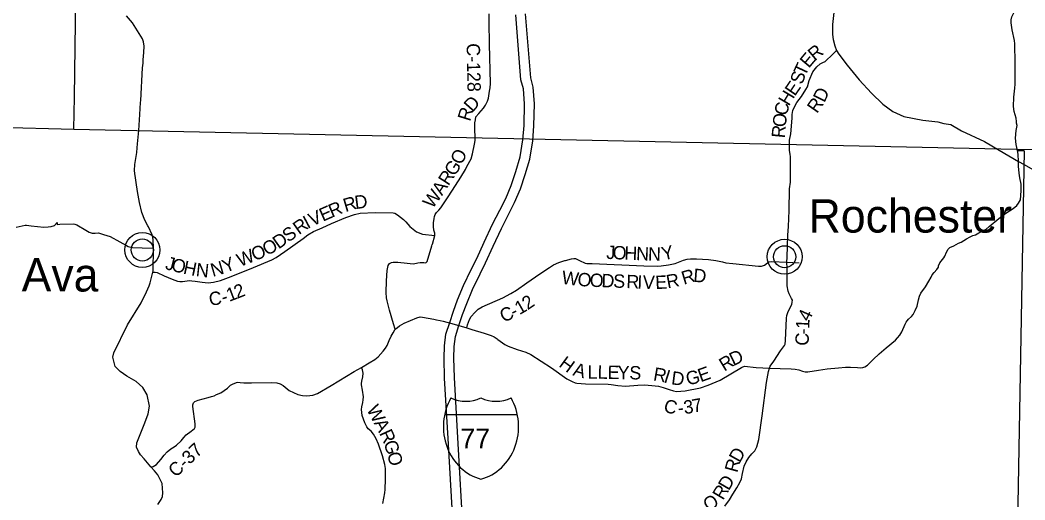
# Model space of a CAD drawing. Extents: x -452339 to 6403467, y -1 to 1814750.
# Drawn here: x -379658 to -357078, y 1620353 to 1631137 of the extents above; entities that cross this region are included whole.
import ezdxf

# ---------------------------------------------------------------- set-up
doc = ezdxf.new("R2010")
doc.units = 0
for name, color, linetype in [('Default', 7, 'Continuous'), ('GM_X_Adjacent_County_Text', 7, 'Continuous'), ('GM_X_County', 7, 'Continuous'), ('GM_X_County_Road', 7, 'Continuous'), ('GM_X_County_Road_Text', 7, 'Continuous'), ('GM_X_Major_River', 7, 'Continuous'), ('GM_X_Minor_Lake_Text', 7, 'Continuous'), ('GM_X_Section', 7, 'Continuous'), ('GM_X_Section_Text', 7, 'Continuous')]:
    doc.layers.add(name, color=color, linetype=linetype)

msp = doc.modelspace()

# ---------------------------------------------------------------- linework, layer by layer
at = {"layer": 'Default'}
for points in [[(-357270, 1628817), (-357270, 1628818), (-357265, 1628856), (-357275, 1628936), (-357318, 1629084), (-357332, 1629193), (-357324, 1629407), (-357306, 1629605), (-357300, 1629697), (-357296, 1630170), (-357303, 1630602), (-357311, 1630676), (-357363, 1630918), (-357387, 1631075), (-357387, 1631139), (-357373, 1631213), (-357301, 1631343), (-357237, 1631443), (-357192, 1631553), (-357162, 1631726), (-357141, 1632254)], [(-369434, 1628434), (-369431, 1628459), (-369440, 1628726), (-369439, 1628828), (-369421, 1628897), (-369414, 1628966), (-369352, 1629041), (-369245, 1629156), (-369196, 1629226), (-369154, 1629311), (-369135, 1629385), (-369106, 1629542), (-369092, 1629616), (-369087, 1629714), (-369109, 1630593), (-369115, 1631092), (-369120, 1631274)], [(-357224, 1627958), (-357232, 1628120), (-357244, 1628204), (-357275, 1628344), (-357290, 1628486), (-357272, 1628652), (-357252, 1628766), (-357270, 1628817)], [(-370394, 1626096), (-370393, 1626098), (-370340, 1626299), (-370341, 1626349), (-370357, 1626413), (-370368, 1626499), (-370364, 1626579), (-370351, 1626676), (-370345, 1626724), (-370330, 1626768), (-370298, 1626814), (-370248, 1626863), (-370203, 1626921), (-370039, 1627165), (-369872, 1627423), (-369756, 1627608), (-369647, 1627777), (-369616, 1627849), (-369523, 1628022), (-369493, 1628130), (-369445, 1628347), (-369434, 1628434)], [(-362819, 1623315), (-362801, 1623357), (-362721, 1623473), (-362569, 1623700), (-362479, 1623824), (-362465, 1623852), (-362456, 1623938), (-362436, 1624435), (-362426, 1624501), (-362396, 1624591), (-362314, 1624744), (-362306, 1624794), (-362302, 1624840), (-362322, 1624882), (-362378, 1624988), (-362398, 1625046), (-362419, 1625168), (-362423, 1625559), (-362431, 1625695), (-362423, 1625807), (-362402, 1626306), (-362388, 1626500), (-362372, 1626854), (-362370, 1627347), (-362345, 1627497), (-362342, 1627996), (-362345, 1628066), (-362353, 1628122), (-362367, 1628205)], [(-357203, 1627695), (-357223, 1627856), (-357224, 1627958)], [(-362819, 1623315), (-362581, 1623307), (-362333, 1623297), (-362237, 1623292), (-362157, 1623276), (-362075, 1623250), (-362015, 1623234), (-361955, 1623232), (-361715, 1623266), (-361523, 1623301), (-361269, 1623321), (-361111, 1623335), (-360995, 1623333), (-360836, 1623330), (-360776, 1623322), (-360722, 1623328), (-360678, 1623342), (-360618, 1623378), (-360490, 1623507), (-360350, 1623635), (-360196, 1623773), (-359988, 1623944), (-359940, 1623994), (-359887, 1624054), (-359841, 1624134), (-359767, 1624305), (-359745, 1624349), (-359727, 1624377), (-359693, 1624417), (-359629, 1624477), (-359591, 1624521), (-359545, 1624608), (-359501, 1624706), (-359467, 1624848), (-359443, 1624934), (-359417, 1624996), (-359314, 1625145), (-359238, 1625267), (-359184, 1625361), (-359158, 1625413), (-359118, 1625467), (-359058, 1625532), (-359022, 1625584), (-359020, 1625612), (-358990, 1625678), (-358898, 1625796), (-358880, 1625830), (-358842, 1625924), (-358799, 1625987), (-358761, 1626029), (-358677, 1626067), (-358569, 1626121), (-358511, 1626147), (-358393, 1626219), (-358311, 1626264), (-358245, 1626292), (-358185, 1626314), (-358113, 1626352), (-358067, 1626380), (-357993, 1626414), (-357945, 1626438), (-357881, 1626495), (-357666, 1626675), (-357504, 1626795), (-357340, 1626906), (-357258, 1626972), (-357222, 1627020), (-357179, 1627097), (-357169, 1627198), (-357164, 1627309), (-357164, 1627451), (-357191, 1627594), (-357203, 1627695)], [(-376673, 1625468), (-376626, 1625470), (-376581, 1625461), (-376421, 1625392), (-376239, 1625317), (-376118, 1625268), (-376068, 1625262), (-376010, 1625265), (-375906, 1625278), (-375851, 1625282), (-375797, 1625275), (-375726, 1625267), (-375668, 1625262), (-375566, 1625248), (-375432, 1625235), (-375313, 1625244), (-375155, 1625284), (-374912, 1625374), (-374415, 1625580), (-374003, 1625747), (-373903, 1625800), (-373712, 1625936), (-373294, 1626228), (-373189, 1626313), (-373064, 1626388), (-372870, 1626471), (-372661, 1626567), (-372340, 1626702), (-372143, 1626764), (-372013, 1626795), (-371675, 1626811), (-371271, 1626807), (-371235, 1626797), (-371179, 1626761), (-371044, 1626652), (-370992, 1626602), (-370897, 1626495), (-370747, 1626376), (-370616, 1626325), (-370340, 1626299)], [(-379747, 1626481), (-379546, 1626525), (-379514, 1626529), (-379410, 1626515), (-379125, 1626484), (-379027, 1626488), (-378958, 1626495), (-378886, 1626520), (-378822, 1626590), (-378822, 1626546), (-378766, 1626551), (-378467, 1626556), (-378428, 1626547), (-378382, 1626533), (-378180, 1626413), (-378105, 1626372), (-378039, 1626351), (-377969, 1626350), (-377899, 1626352), (-377781, 1626320), (-377634, 1626276), (-377416, 1626156), (-377270, 1626068), (-377226, 1626047), (-377169, 1626035), (-377131, 1626027), (-376912, 1626020), (-376659, 1626013)], [(-371227, 1624187), (-371266, 1624309), (-371354, 1624621), (-371409, 1624824), (-371426, 1624892), (-371429, 1625011), (-371421, 1625279), (-371408, 1625510), (-371385, 1625624), (-371359, 1625664), (-371312, 1625689), (-371272, 1625697), (-371172, 1625694), (-370958, 1625671), (-370890, 1625664), (-370820, 1625662), (-370720, 1625681), (-370670, 1625686), (-370582, 1625686), (-370542, 1625683), (-370530, 1625689), (-370512, 1625709), (-370403, 1626062), (-370394, 1626096)], [(-367403, 1625734), (-367265, 1625773), (-367215, 1625780), (-367179, 1625777), (-367089, 1625736), (-366960, 1625677), (-366923, 1625665), (-366803, 1625663), (-365639, 1625616), (-365325, 1625606), (-365251, 1625611), (-365089, 1625634), (-364934, 1625669), (-364749, 1625743), (-364666, 1625764), (-364590, 1625774), (-364458, 1625774), (-364185, 1625755), (-364021, 1625736), (-363871, 1625700), (-363798, 1625682), (-363640, 1625667), (-363063, 1625603), (-362997, 1625604), (-362932, 1625631), (-362864, 1625683), (-362833, 1625703), (-362767, 1625710), (-362431, 1625695)], [(-369615, 1624217), (-369603, 1624288), (-369557, 1624408), (-369522, 1624472), (-369440, 1624568), (-369363, 1624637), (-369274, 1624689), (-368810, 1624898), (-368628, 1624991), (-368503, 1625066), (-368270, 1625228), (-368078, 1625364), (-367997, 1625421), (-367762, 1625580), (-367669, 1625636), (-367554, 1625690), (-367415, 1625730), (-367403, 1625734)], [(-362431, 1625695), (-362154, 1625682)], [(-376718, 1621099), (-376664, 1621102), (-376628, 1621126), (-376590, 1621152), (-376496, 1621260), (-376422, 1621355), (-376350, 1621433), (-376270, 1621501), (-376198, 1621547), (-376141, 1621583), (-376035, 1621684), (-375979, 1621756), (-375925, 1621812), (-375815, 1621896), (-375741, 1621955), (-375723, 1621985), (-375727, 1622059), (-375779, 1622455), (-375773, 1622493), (-375760, 1622531), (-375732, 1622566), (-375658, 1622598), (-375432, 1622654), (-375354, 1622678), (-375300, 1622694), (-375244, 1622719), (-375150, 1622759), (-375070, 1622809), (-374998, 1622863), (-374968, 1622893), (-374928, 1622931), (-374888, 1622955), (-374796, 1622988), (-374764, 1622996), (-374710, 1622990), (-374630, 1622986), (-374458, 1622986), (-374013, 1622991), (-373885, 1622981), (-373817, 1622965), (-373749, 1622923), (-373613, 1622813), (-373416, 1622719), (-373315, 1622697), (-373213, 1622692), (-373083, 1622710), (-372977, 1622744), (-372671, 1622923), (-372151, 1623236), (-371984, 1623332), (-371812, 1623433), (-371686, 1623509), (-371614, 1623565), (-371496, 1623698), (-371446, 1623764), (-371408, 1623820), (-371364, 1623932), (-371322, 1624031), (-371276, 1624107), (-371227, 1624187), (-371175, 1624231), (-371135, 1624267), (-371027, 1624325), (-370745, 1624442), (-370671, 1624464), (-370617, 1624462), (-370359, 1624415), (-370301, 1624402), (-370301, 1624402)], [(-370301, 1624402), (-370215, 1624383), (-370153, 1624369), (-369900, 1624305), (-369615, 1624217), (-369507, 1624182), (-369231, 1624102), (-369073, 1624050), (-369007, 1624020), (-368936, 1623972), (-368936, 1623971)], [(-368936, 1623971), (-368919, 1623960), (-368761, 1623848), (-368693, 1623810), (-368485, 1623737), (-368293, 1623675), (-368179, 1623619), (-367715, 1623325), (-367371, 1623075), (-367249, 1623011), (-367187, 1622985), (-367143, 1622973), (-366951, 1622964), (-366441, 1622953), (-366377, 1622943), (-366229, 1622921), (-366053, 1622911), (-365779, 1622934), (-365621, 1622942), (-365388, 1622920), (-365314, 1622906), (-365206, 1622882), (-365070, 1622832), (-364976, 1622807), (-364906, 1622793), (-364712, 1622805), (-364370, 1622872), (-364198, 1622928), (-363924, 1623045), (-363447, 1623332), (-363429, 1623340), (-363377, 1623356), (-363119, 1623330), (-362819, 1623315)], [(-371505, 1620272), (-371461, 1620511), (-371453, 1620585), (-371449, 1620817), (-371450, 1621060), (-371464, 1621148), (-371514, 1621340), (-371600, 1621604), (-371656, 1621728), (-371714, 1621829), (-371770, 1621901), (-371834, 1621951), (-371868, 1621995), (-371910, 1622083), (-371967, 1622249), (-371981, 1622317), (-371989, 1622383), (-371981, 1622445), (-371953, 1622545), (-371945, 1622603), (-371943, 1622669), (-371963, 1622816), (-371985, 1622940), (-371987, 1622972), (-371981, 1623022), (-371959, 1623120), (-371949, 1623200), (-371961, 1623274), (-371984, 1623332)], [(-363820, 1620210), (-363716, 1620354), (-363640, 1620485), (-363550, 1620623), (-363482, 1620745), (-363448, 1620828), (-363426, 1620948), (-363387, 1621108), (-363345, 1621212), (-363285, 1621303), (-363217, 1621391), (-363149, 1621459), (-363101, 1621545), (-363055, 1621710), (-362980, 1622245), (-362882, 1622990), (-362837, 1623237), (-362819, 1623315)]]:
    msp.add_lwpolyline(points, dxfattribs=at)
for centre, major_axis, start_param, end_param in [((-369055, 1622001), (0, -1211), 4.15077, 6.05619), ((-369639, 1623536), (0, -966), 5.88324, 6.683049), ((-369546, 1622001), (0, -1211), 0.227007, 2.13242), ((-368962, 1623536), (0, -966), 5.883359, 6.683012)]:
    msp.add_ellipse(centre, major_axis=major_axis, ratio=0.9, start_param=start_param, end_param=end_param, dxfattribs=at)
at = {"layer": 'GM_X_County_Road'}
for points in [[(-361353, 1631446), (-361401, 1631037), (-361398, 1630812), (-361384, 1630698), (-361347, 1630556), (-361309, 1630456), (-361259, 1630372), (-361075, 1630126), (-360803, 1629795), (-360524, 1629493), (-360268, 1629246), (-360049, 1629083), (-359797, 1628970), (-359370, 1628890), (-359033, 1628851), (-358900, 1628816), (-358744, 1628790), (-358501, 1628647), (-357982, 1628410), (-357655, 1628213), (-357224, 1627958), (-357097, 1627889), (-356492, 1627544)], [(-369913, 1619506), (-370040, 1621735), (-370119, 1623092), (-370131, 1623539), (-370122, 1623818), (-370089, 1624076), (-370004, 1624339), (-369920, 1624594), (-369825, 1624848), (-369691, 1625170), (-369519, 1625534), (-369394, 1625777), (-369226, 1626146), (-369039, 1626549), (-368876, 1626866), (-368744, 1627128), (-368623, 1627420), (-368520, 1627733), (-368418, 1628062), (-368357, 1628447), (-368330, 1628770), (-368321, 1629253), (-368344, 1629595), (-368402, 1629796), (-368516, 1631255)], [(-369693, 1619518), (-369820, 1621748), (-369899, 1623102), (-369911, 1623538), (-369902, 1623800), (-369873, 1624028), (-369795, 1624271), (-369713, 1624521), (-369621, 1624767), (-369490, 1625080), (-369321, 1625437), (-369196, 1625681), (-369026, 1626054), (-368842, 1626452), (-368680, 1626767), (-368544, 1627036), (-368416, 1627344), (-368310, 1627666), (-368203, 1628012), (-368138, 1628421), (-368110, 1628758), (-368101, 1629258), (-368126, 1629633), (-368184, 1629836), (-368297, 1631275)]]:
    msp.add_lwpolyline(points, dxfattribs=at)
at = {"layer": 'GM_X_County_Road_Text'}
for centre, radius in [((-376909, 1625971), 393), ((-376909, 1625971), 249), ((-362476, 1625817), 393), ((-362476, 1625817), 249)]:
    msp.add_circle(centre, radius, dxfattribs=at)
at = {"layer": 'GM_X_Major_River'}
for points in [[(-377024, 1628266), (-377018, 1628356), (-376992, 1628652), (-376965, 1629012), (-376949, 1629285), (-376943, 1629327), (-376906, 1630063), (-376895, 1630171), (-376889, 1630245), (-376875, 1630412), (-376866, 1630551), (-376886, 1630647), (-376907, 1630715), (-377132, 1631076), (-377263, 1631230)], [(-376760, 1625168), (-376735, 1625232), (-376673, 1625468), (-376664, 1625501), (-376659, 1626013), (-376667, 1626200), (-376677, 1626252), (-376688, 1626311), (-376772, 1626491), (-376784, 1626512), (-376855, 1626643), (-376925, 1626813), (-376976, 1627035), (-377017, 1627282), (-377049, 1627489), (-377067, 1627594), (-377079, 1627688), (-377088, 1627757), (-377082, 1627889), (-377075, 1627933), (-377031, 1628164), (-377024, 1628266)], [(-376563, 1620247), (-376487, 1620363), (-376459, 1620433), (-376449, 1620509), (-376466, 1620722), (-376560, 1620914), (-376634, 1621008), (-376718, 1621099), (-376870, 1621274), (-376954, 1621366), (-376999, 1621438), (-377043, 1621541), (-377034, 1621639), (-376942, 1621864), (-376855, 1622085), (-376782, 1622286), (-376746, 1622461), (-376805, 1622717), (-376902, 1622883), (-377053, 1623015), (-377258, 1623132), (-377408, 1623239), (-377523, 1623349), (-377570, 1623560), (-377550, 1623657), (-377242, 1624285), (-376938, 1624780), (-376814, 1625027), (-376760, 1625168)]]:
    msp.add_lwpolyline(points, dxfattribs=at)
at = {"layer": 'GM_X_Minor_Lake_Text'}
msp.add_line((-370115, 1622274), (-368484, 1622274), dxfattribs=at)
at = {"layer": 'GM_X_Section'}
msp.add_lwpolyline([(-362367, 1628205), (-362367, 1628209), (-362369, 1628293), (-362367, 1628437), (-362336, 1628580), (-362304, 1628929), (-362308, 1629015), (-362290, 1629107), (-362250, 1629203), (-362204, 1629284), (-362152, 1629350), (-362096, 1629418), (-362002, 1629574), (-361966, 1629636), (-361927, 1629779), (-361845, 1629977), (-361755, 1630089), (-361679, 1630157), (-361615, 1630181), (-361569, 1630208), (-361527, 1630240), (-361429, 1630336), (-361309, 1630456)], dxfattribs=at)
at = {"layer": 'GM_X_Section_Text'}
for p, q in [((-378437, 1629407), (-378391, 1632815)), ((-378448, 1628686), (-378437, 1629407)), ((-383695, 1628810), (-378448, 1628686)), ((-378448, 1628686), (-345663, 1627986)), ((-357093, 1628200), (-357520, 1603979)), ((-357244, 1628204), (-357093, 1628200)), ((-357093, 1628200), (-357244, 1628204))]:
    msp.add_line(p, q, dxfattribs=at)

# ---------------------------------------------------------------- texts
at = {"layer": 'Default'}
msp.add_text('77', height=447.7, dxfattribs=at).set_placement((-369763, 1621510))
at = {"layer": 'GM_X_Adjacent_County_Text'}
for s, p in [('Rochester', (-361939, 1626361)), ('Ava', (-379624, 1625037))]:
    msp.add_text(s, height=750, rotation=0, dxfattribs=at).set_placement(p)
at = {"layer": 'GM_X_County'}
for s, rotation, p in [('C-128', 271.1062, (-369624, 1630614)), ('R', 39.7046, (-361800, 1630204)), ('E', 50.0035, (-361934, 1630042)), ('T', 65.0949, (-362017, 1629856)), ('S', 70.4668, (-362082, 1629672)), ('E', 55.5539, (-362248, 1629412)), ('D', 48.6523, (-369491, 1629052)), ('H', 58.8932, (-362382, 1629189)), ('D', 63.867, (-361585, 1629268)), ('R', 72.6895, (-369548, 1628846)), ('C', 77.0893, (-362427, 1628973)), ('R', 55.4038, (-361749, 1629024)), ('O', 84.3006, (-362452, 1628720)), ('R', 84.5197, (-362475, 1628475)), ('O', 64.7446, (-369734, 1627867)), ('G', 57.6471, (-369895, 1627608)), ('R', 56.8631, (-370032, 1627398)), ('W', 54.0288, (-370390, 1626882)), ('A', 56.9167, (-370176, 1627177)), ('R', 16.4499, (-372346, 1626821)), ('D', 7.3713, (-372122, 1626888)), ('E', 23.6966, (-372854, 1626603)), ('R', 23.2503, (-372649, 1626693)), ('I', 27.965, (-373199, 1626440)), ('V', 24.1777, (-373094, 1626495)), ('S', 35.1543, (-373633, 1626131)), ('R', 35.3725, (-373391, 1626303)), ('D', 35.3468, (-373848, 1625979)), ('W', 22.1138, (-374712, 1625585)), ('O', 22.1968, (-374390, 1625716)), ('O', 28.7901, (-374111, 1625832)), ('J', 357.6291, (-366488, 1625771)), ('O', 357.6242, (-366347, 1625765)), ('H', 357.6281, (-366083, 1625754)), ('N', 357.6279, (-365819, 1625743)), ('N', 358.6469, (-365550, 1625732)), ('Y', 12.385, (-365208, 1625733)), ('J', 345.7633, (-376414, 1625543)), ('O', 345.8408, (-376277, 1625508)), ('Y', 22.2968, (-375042, 1625450)), ('H', 348.2621, (-376007, 1625441)), ('N', 353.7904, (-375717, 1625382)), ('N', 16.2301, (-375328, 1625364)), ('D', 355.9567, (-364535, 1625254)), ('W', 353.1752, (-367497, 1625210)), ('O', 355.071, (-367141, 1625167)), ('O', 358.3354, (-366860, 1625143)), ('D', 357.8283, (-366597, 1625136)), ('S', 357.7996, (-366333, 1625126)), ('R', 357.7941, (-366038, 1625114)), ('I', 357.8312, (-365792, 1625105)), ('V', 358.0127, (-365668, 1625100)), ('E', 2.3302, (-365379, 1625091)), ('R', 10.6885, (-365107, 1625106)), ('R', 16.7635, (-364743, 1625186)), ('1', 20.7833, (-374958, 1624803)), ('2', 21.5625, (-374781, 1624870)), ('C', 6.379, (-375399, 1624718)), ('-', 18.0411, (-375089, 1624760)), ('2', 34.5874, (-368251, 1624612)), ('C', 24.8665, (-368793, 1624333)), ('1', 29.6253, (-368436, 1624505)), ('-', 26.8489, (-368559, 1624442)), ('4', 65.4531, (-361924, 1624344)), ('1', 87.9284, (-361924, 1624190)), ('C', 86.0979, (-361945, 1623810)), ('-', 88.0035, (-361928, 1624067)), ('H', 323.8521, (-367569, 1623364)), ('R', 31.271, (-363834, 1623233)), ('D', 25.5354, (-363630, 1623357)), ('A', 344.4167, (-367251, 1623157)), ('L', 0.8323, (-366904, 1623074)), ('L', 358.8814, (-366682, 1623077)), ('E', 358.8771, (-366458, 1623073)), ('Y', 358.8796, (-366233, 1623068)), ('S', 358.8786, (-365969, 1623063)), ('R', 349.9692, (-365443, 1623042)), ('E', 19.7885, (-364364, 1622995)), ('I', 342.2562, (-365211, 1623002)), ('D', 352.6509, (-365036, 1622952)), ('G', 13.2592, (-364657, 1622924)), ('7', 10.961, (-364527, 1622310)), ('W', 298.1998, (-371879, 1622389)), ('C', 346.1427, (-365213, 1622336)), ('-', 5.7938, (-364862, 1622269)), ('3', 7.5945, (-364730, 1622282)), ('A', 298.0656, (-371715, 1622082)), ('R', 294.6307, (-371593, 1621854)), ('C-37', 43.571, (-376157, 1620844)), ('G', 288.458, (-371494, 1621638)), ('D', 60.8601, (-363485, 1621171)), ('O', 284.2103, (-371412, 1621393)), ('R', 74.6904, (-363542, 1620951)), ('D', 59.6092, (-363733, 1620546)), ('R', 58.9422, (-363862, 1620331)), ('O', 32.4395, (-364189, 1620082))]:
    msp.add_text(s, height=300, rotation=rotation, dxfattribs=at).set_placement(p)

doc.saveas('drawing.dxf')
